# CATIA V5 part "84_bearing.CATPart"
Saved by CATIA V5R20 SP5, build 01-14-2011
Part number: 84_bearing
Bounding box of the stored display mesh (mm): x -13.957 to 13.957, y 19.362 to 47.362, z -82.294 to -70.294
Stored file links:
  C:\Documents and Settings\anizard\Bureau\13\84_bearing.CATPart
  C:\Documents and Settings\anizard\Bureau\13\anizard.CATProduct
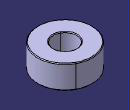
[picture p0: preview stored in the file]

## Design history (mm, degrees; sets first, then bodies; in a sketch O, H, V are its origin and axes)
Set1
  Plane1: linked copy from another document
  Point1: linked copy from another document
  Plane2: linked copy from another document
  Line1: linked copy from another document
  Plane3: linked copy from another document
  Point2: linked copy from another document
Body1 (main body)
  Sketch1 on Plane1, origin (0, 0, 0), H (0, 1, 0), V (0, 0, 1)
    line L1 (39.7155, -70.2938) -> (47.0084, -70.2938)
    line L2 (47.3619, -70.6474) -> (47.3619, -81.9403)
    line L3 (47.0084, -82.2938) -> (39.7155, -82.2938)
    line L4 (39.3619, -81.9403) -> (39.3619, -70.6474)
    line L5 (47.3619, -70.6474) -> (47.0084, -70.2938)
    line L6 (39.7155, -70.2938) -> (39.3619, -70.6474)
    line L7 (39.7155, -82.2938) -> (39.3619, -81.9403)
    line L8 (47.3619, -81.9403) -> (47.0084, -82.2938)
    reference projected point E1 (39.3619, -70.2938) from Point1
    reference intersected line E2 through (0, -82.2938) direction (1, 0) from Plane2
    reference intersected line E3 through (0, -70.2938) direction (1, 0) from Plane3
    reference projected point E4 (47.3619, -70.2938) from Point2
    angle L2 L5 = 45
    length L5 = 0.5
    angle L1 L6 = 45
    length L6 = 0.5
    angle L3 L7 = 45
    length L7 = 0.5
    angle L2 L8 = 45
    length L8 = 0.5
    horizontal: L1 H, L3 H
    vertical: L2 V, L4 V
    coincidence: L4 E1, L3 E2, L1 E3, L2 E4
  Shaft1: profile Sketch1, axis Line1, angle 360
